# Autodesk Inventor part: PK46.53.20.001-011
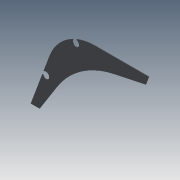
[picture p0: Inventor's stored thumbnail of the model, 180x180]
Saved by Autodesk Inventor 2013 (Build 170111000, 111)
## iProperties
Created: 2005-03
Part Number: PK46.53.20.001-011
Material: Generic
Document SubType Name: Modeling
Designer: tedescj
Manufacturer: Standard
Standards Organization: Custom
Mass: 4751.84 g
Surface Area: 3132.04 cm^2
Volume: 604.56 cm^3
Density: 7.86 g/cm^3
Author: tedescj
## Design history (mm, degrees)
derived "PK46.53.20.001-01.ipt"
  sketch "Эскиз1"
    geometry: L1 (-264.331, 0)-(-690, 0) reference; L2 (-690, 0)-(-665.652, -65.629) reference; L3 (170, -646.916)-(240, -646.916) reference; L4 (240, -646.916)-(91.941, -247.826) reference; L5 (170, -646.916)-(32.608, -429.61) reference; L6 (-414.127, -118.858)-(-665.652, -65.629) reference; L7 (0, 0)-(-559.054, -803.691) reference; L8 (148.869, -401.272)-(144.181, -403.012) reference; L9 (137.737, -371.269)-(133.05, -373.008) reference; L10 (-89.677, -42.515)-(-91.976, -46.956) reference; L11 (-119.608, -28.638)-(-121.512, -33.261) reference; L12 (-89.677, -42.515)-(-104.341, -34.926) reference; L13 (-119.608, -28.638)-(-104.341, -34.926) reference; L14 (-103.508, -35.71)-(-103.28, -35.269) reference; L15 (143.908, -386.046)-(143.303, -386.271) reference; A1 r 380 centre (-264.331, -380) between (91.941, -247.826) and (-264.331, 0) reference; A2 r 25.5 centre (120, -394.916) between (144.181, -403.012) and (133.05, -373.008) reference; A3 r 25.5 centre (-115, -57.916) between (-91.976, -46.956) and (-121.512, -33.261) reference; A4 r 700 centre (-559.054, -803.691) between (32.608, -429.61) and (-414.127, -118.858) reference; 1 further point
feature "Solid1::PK46.53.20.001-01.ipt" dims "d0" = 10
tag "TaggingFeature1"
body "Solid1"
